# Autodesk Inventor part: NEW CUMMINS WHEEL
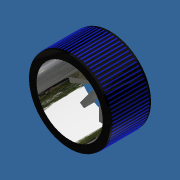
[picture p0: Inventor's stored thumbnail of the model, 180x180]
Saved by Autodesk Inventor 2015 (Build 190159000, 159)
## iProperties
Created: 2014-11
Part Number: NEW CUMMINS WHEEL
Material: Generic
Document SubType Name: Modeling
Designer: caovt
Density: 1 g/cm^3
Appearance: Default
Author: caovt
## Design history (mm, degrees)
sketch "Sketch1"
  geometry: C1 r 25.4 at (0, 0); 1 further point
  constraints: 1 centre point, 1 coincident
  dimensions: "d0" = 50.8 diameter of C1
extrude "Extrusion1" new body sketch "Sketch1" distance "d1" = 25.4; taper "d2" = 0 deg
sketch "Sketch2"
  geometry: C1 r 25.4 at (0, 0) reference; C2 r 20.638 at (0, 0)
  constraints: 1 centre point, 1 coincident
  dimensions: "d3" = 41.275 diameter of C2
extrude "Extrusion2" cut sketch "Sketch2" distance "d4" = 19.05; taper "d5" = 0 deg
sketch "Sketch3"
  geometry: L1 (0, 0)-(-0.635, 0); L2 (0, 0)-(0.635, 0); L3 (-0.635, 0)-(-0.635, 20.628); L4 (0.635, 0)-(0.635, 20.628); L5 (0.635, 0)-(10.873, 17.541); L6 (0.635, 1.926)-(10.043, 18.029); A1 r 20.638 centre (0, 0) between (-0.635, 20.628) and (0.635, 20.628) reference; A2 r 20.638 centre (0, 0) between (10.873, 17.541) and (10.043, 18.029) reference
  constraints: 12 end point, 6 point on circle, 2 horizontal, 2 vertical, 1 point on line
  dimensions: "d6" = 0.635 distance of L1.start L1.end; "d7" = 0.635 distance of L1.start L2.end; "d10" = 0.025 deg angle of L6 L5
extrude "Extrusion4" cut sketch "Sketch3" distance "d11" = 19.05; taper "d12" = 0 deg
pattern_circular "Circular Pattern1" dims angle "d14" = 360 deg
workaxis "Work Axis1"
workplane "Work Plane1"
sketch "Sketch4"
  geometry: L1 (-0.289, 1.27)-(0.346, 1.27); L2 (0.346, 1.27)-(0.346, 24.13); L3 (0.346, 24.13)-(-0.289, 24.13); L4 (-0.289, 24.13)-(-0.289, 1.27); L5 (-25.4, 0)-(25.4, 0) reference; 1 further point
  constraints: 8 end point, 2 parallel, 1 horizontal, 1 perpendicular
  dimensions: "d16" = 0.635 distance between parallel lines of L4 L2; "d17" = 22.86 distance of L3.end L1.start; "d18" = 1.27 distance between parallel lines of L5 L1
extrude "Extrusion5" join sketch "Sketch4" distance "d19" = 0.254; taper "d20" = 0 deg
sketch "Sketch5"
  geometry: C1 r 25.4 at (0, 0) reference; C2 r 2.286 at (0, 0)
  constraints: 1 centre point, 1 coincident
  dimensions: "d24" = 4.572 diameter of C2
extrude "Extrusion6" cut sketch "Sketch5" distance "d25" = 5.08; taper "d26" = 0 deg
body "Solid1"
pattern_circular "Circular Pattern2" dims angle "d22" = 360 deg
